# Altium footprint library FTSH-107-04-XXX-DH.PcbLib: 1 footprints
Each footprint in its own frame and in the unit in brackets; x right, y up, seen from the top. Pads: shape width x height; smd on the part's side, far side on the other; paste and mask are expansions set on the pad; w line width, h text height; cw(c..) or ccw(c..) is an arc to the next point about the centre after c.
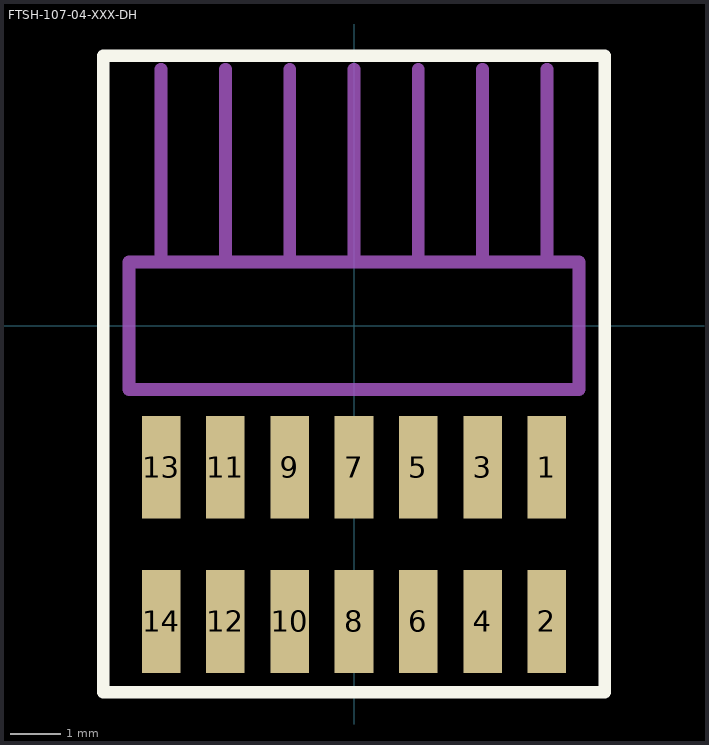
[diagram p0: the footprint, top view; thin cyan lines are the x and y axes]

## FTSH-107-04-XXX-DH [mil]
pads (14):
  rect 30x80 smd mask+2: 1(150,-110) 2(150,-230) 3(100,-110) 4(100,-230) 5(50,-110) 6(50,-230) 7(0,-110) 8(0,-230) 9(-50,-110) 10(-50,-230) 11(-100,-110) 12(-100,-230) 13(-150,-110) 14(-150,-230)
Top Overlay:
  lines w10: -195,-285 -195,210 195,210 195,-285 -195,-285
Mechanical 1:
  lines w10: -150,49.5 -150,199.5 ; -100,49.5 -100,199.5 ; -50,49.5 -50,199.5 ; 0,49.5 0,199.5 ; 50,49.5 50,199.5 ; 100,49.5 100,199.5 ; 150,49.5 150,199.5 ; -175,-49.5 -175,49.5 175,49.5 175,-49.5 -175,-49.5
  text "J1" at -17.57,-18 h30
